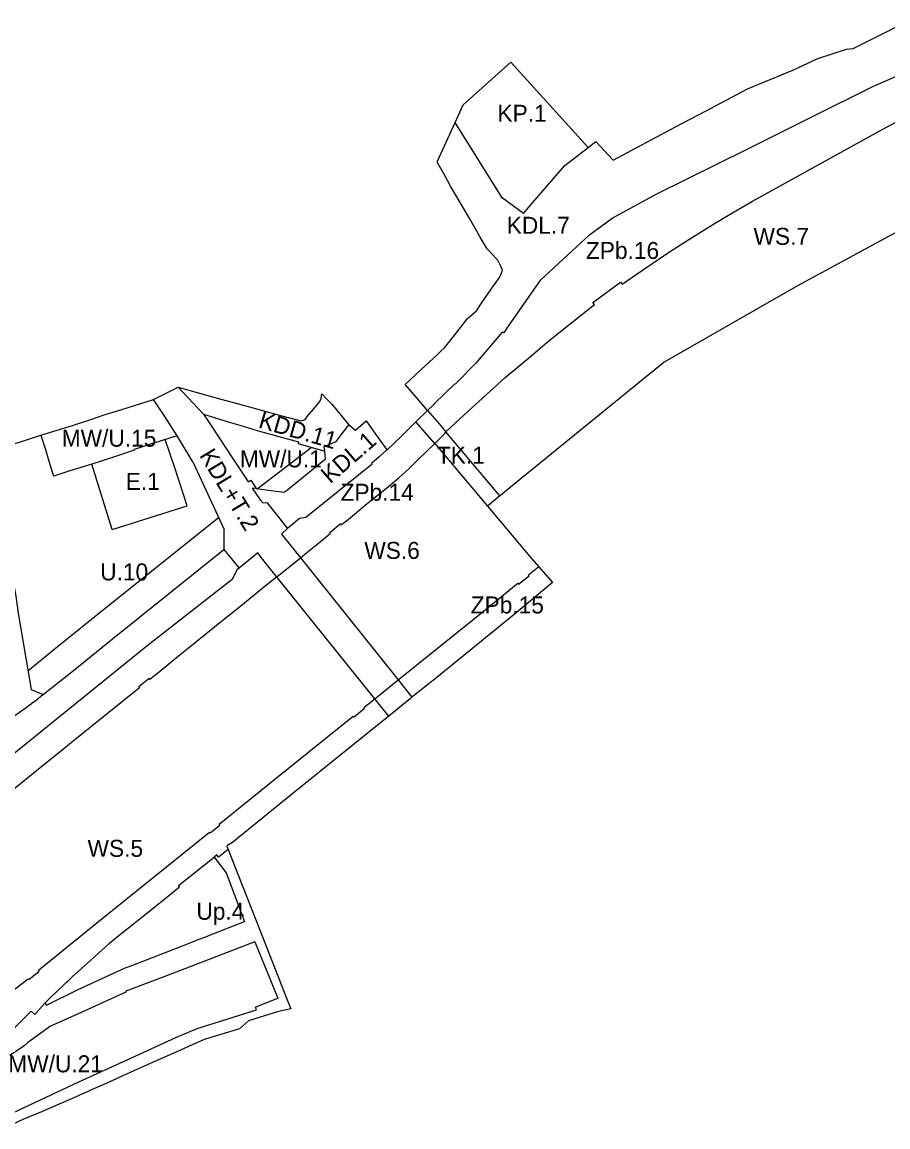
# Model space of a CAD drawing. Extents: x 7421697 to 7426767, y 5545731 to 5547485.
# Drawn here: x 7424808 to 7425420, y 5546077 to 5546858 of the extents above; entities that cross this region are included whole.
import ezdxf

# ---------------------------------------------------------------- set-up
doc = ezdxf.new("R2010")
doc.units = 0
for name, color, linetype in [('LIN_Linia Zabudowy Nieprzekraczalna', 7, 'Continuous'), ('LIN_linie rozgraniczające terenu WS', 7, 'Continuous'), ('LIN_linie_rozgraniczajace', 7, 'Continuous'), ('TXT_oznaczenia_przeznaczen', 7, 'Continuous')]:
    doc.layers.add(name, color=color, linetype=linetype)

msp = doc.modelspace()

# ---------------------------------------------------------------- linework, layer by layer
at = {"layer": 'LIN_Linia Zabudowy Nieprzekraczalna'}
msp.add_line((7424974.16, 5546528.08), (7425012.34, 5546557.27), dxfattribs=at)
msp.add_lwpolyline([(7424812.12, 5546399.5), (7424832.88, 5546416.23), (7424859.51, 5546437.7), (7424946.91, 5546507.81)], dxfattribs=at)
at = {"layer": 'LIN_linie rozgraniczające terenu WS'}
for p, q in [((7424988.11, 5546465.87), (7425004.76, 5546479.32)), ((7425057.27, 5546379.65), (7425073.85, 5546392.93))]:
    msp.add_line(p, q, dxfattribs=at)
msp.add_lwpolyline([(7425099.74, 5546560.06), (7425106.95, 5546567.12), (7425107.66, 5546568.17)], dxfattribs=at)
at = {"layer": 'LIN_linie_rozgraniczajace'}
for p, q in [((7425099.74, 5546560.06), (7425086.39, 5546575.21)), ((7425145.83, 5546523), (7425107.66, 5546568.17)), ((7425099.74, 5546560.06), (7425137.02, 5546515.83)), ((7424871.65, 5546499.22), (7424857.22, 5546545.47)), ((7424972.54, 5546207.92), (7424988.84, 5546168.02))]:
    msp.add_line(p, q, dxfattribs=at)
for points in [[(7424799.61, 5546558.88), (7424821.33, 5546565.81), (7424832.92, 5546569.44), (7424844.36, 5546573.07), (7424855.79, 5546576.7), (7424866.75, 5546580.41), (7424878.58, 5546584.06), (7424900.98, 5546591.12), (7424918.38, 5546599.75), (7424933.46, 5546595.59), (7424948.55, 5546591.43), (7424961.05, 5546588.01), (7424991.7, 5546579.66), (7425005.24, 5546575.97), (7425008.11, 5546576.92), (7425009.64, 5546579), (7425014.08, 5546584.36), (7425018.52, 5546589.72), (7425019.53, 5546591.91), (7425019.91, 5546595.02), (7425023.45, 5546591.36), (7425027, 5546587.7), (7425038.9, 5546573.3), (7425041.24, 5546571.43), (7425043.82, 5546569.36), (7425051.22, 5546576.08), (7425055.05, 5546570.66), (7425065.79, 5546555.44), (7425065.84, 5546555.36), (7425076.12, 5546565.29), (7425086.39, 5546575.21), (7425094.68, 5546583.27), (7425086.78, 5546592.47), (7425078.87, 5546601.67), (7425090.16, 5546612.2), (7425101.46, 5546622.74), (7425104.03, 5546625.14), (7425106.59, 5546627.55), (7425114.78, 5546637.95), (7425122.96, 5546648.35), (7425129.19, 5546653.8), (7425133.85, 5546660.53), (7425139.71, 5546668.94), (7425145.58, 5546677.35), (7425146.62, 5546679.93), (7425147.67, 5546682.52), (7425146.16, 5546685.76), (7425144.66, 5546689.01), (7425140.78, 5546693.22), (7425136.89, 5546697.42), (7425134.31, 5546701.86), (7425131.72, 5546706.29), (7425124.49, 5546718.66), (7425117.69, 5546730.27), (7425110.89, 5546741.88), (7425106.58, 5546749.77), (7425102.27, 5546757.66), (7425101.36, 5546759.07), (7425114.14, 5546786.84), (7425119.92, 5546799.25), (7425153.43, 5546829.48), (7425208.12, 5546769.05), (7425213.67, 5546773.31), (7425225.89, 5546760.2), (7425269.84, 5546783.7), (7425291.13, 5546794.9), (7425320.74, 5546810.47), (7425352.83, 5546823.71), (7425370.5, 5546831.95), (7425390.91, 5546838.71), (7425395.55, 5546839), (7425432.72, 5546857.72)], [(7425150.26, 5546640.53), (7425174.69, 5546675.57), (7425209.13, 5546707.54), (7425225.24, 5546719.13), (7425256.82, 5546736.38), (7425320.57, 5546768.05), (7425366.22, 5546790.77), (7425409.84, 5546812.52), (7425454.91, 5546831.93), (7425462.33, 5546834.59), (7425472.1, 5546838.09), (7425490.62, 5546843.04), (7425509.4, 5546848.46), (7425520.77, 5546850.87), (7425531.3, 5546848.51)], [(7425168.77, 5546622.63), (7425179.18, 5546631.49), (7425195.51, 5546644.63), (7425212.72, 5546658.14), (7425211.46, 5546659.7), (7425231.15, 5546674.09), (7425232.29, 5546672.55), (7425246.51, 5546682.57), (7425265.76, 5546695.52), (7425281.92, 5546705.87), (7425297.56, 5546715.53), (7425301, 5546717.59), (7425312.66, 5546724.34), (7425324.32, 5546731.1), (7425413.84, 5546780.71), (7425439.34, 5546794.38), (7425453.06, 5546801.44), (7425472.41, 5546810.87), (7425492.07, 5546819.93), (7425518.89, 5546831.06), (7425536.41, 5546837.33), (7425547.13, 5546840.63)], [(7425162.42, 5546722.56), (7425147.46, 5546733.56), (7425114.14, 5546786.84)], [(7425162.42, 5546722.56), (7425168.95, 5546730.11), (7425191.75, 5546756.46), (7425208.12, 5546769.05)], [(7425432.35, 5546712.59), (7425356.22, 5546671.39), (7425261.83, 5546617.35), (7425154.53, 5546530.08), (7425146.14, 5546523.24), (7425145.83, 5546523), (7425138.13, 5546516.73), (7425137.02, 5546515.83), (7425168.21, 5546478.7), (7425173.22, 5546472.96), (7425183.03, 5546461.75), (7425155.91, 5546439.18), (7425100.05, 5546393.63), (7425083.65, 5546380.67), (7425082.63, 5546379.87), (7425067.33, 5546367.48), (7425050.61, 5546354.02), (7424999.71, 5546312.89), (7424956.76, 5546278.19), (7424952.83, 5546275.68), (7424953.78, 5546273.19), (7424958.33, 5546261.26), (7424978.44, 5546210.29), (7424995.51, 5546167.01), (7424998.07, 5546160.52), (7424989.29, 5546158.65), (7424968.14, 5546152.12), (7424961.67, 5546146.44), (7424936.81, 5546138.91), (7424925.75, 5546133.94), (7424919.95, 5546131.4), (7424904.46, 5546124.56), (7424894.34, 5546120.04), (7424879.74, 5546113.49), (7424867.95, 5546108.17), (7424865.81, 5546107.22), (7424857.48, 5546103.49), (7424853.07, 5546101.52), (7424849.19, 5546099.79), (7424846.77, 5546098.71), (7424821.65, 5546087.94), (7424808.45, 5546082.3), (7424797.36, 5546077.18)], [(7425150.26, 5546640.53), (7425148.4, 5546638.24), (7425147.69, 5546638.87), (7425128.58, 5546616.6), (7425124.42, 5546612.36), (7425120.26, 5546608.12), (7425114.18, 5546601.86), (7425113.89, 5546602.14), (7425106.79, 5546595.23), (7425099.68, 5546588.31), (7425098.77, 5546587.39), (7425094.68, 5546583.27)], [(7425107.66, 5546568.17), (7425117.59, 5546577.52), (7425149.58, 5546606.7), (7425168.77, 5546622.63)], [(7424918.38, 5546599.75), (7424936.3, 5546580.66), (7424937.67, 5546578.57), (7424942.28, 5546571.55), (7424956.7, 5546549.56), (7424965.17, 5546536.87), (7424967.77, 5546532.99), (7424969.61, 5546534.13), (7424973.56, 5546528.16), (7424992.94, 5546525.64), (7424995.91, 5546527.54), (7425022.52, 5546549.28), (7425021.96, 5546554.53), (7425021.6, 5546557.85), (7425030.05, 5546561.43), (7425038.9, 5546573.3)], [(7424928.77, 5546547.03), (7424917.59, 5546565.52), (7424912.66, 5546573.16), (7424912.72, 5546573.21), (7424908.42, 5546579.75), (7424901, 5546591.13)], [(7424936.3, 5546580.66), (7424953.81, 5546575.36), (7424961.85, 5546572.93), (7424974.2, 5546569.2), (7424989.56, 5546564.96), (7425003.36, 5546561.07), (7425003.1, 5546559.9), (7425021.96, 5546554.53)], [(7425094.68, 5546583.27), (7425102.77, 5546573.86), (7425107.66, 5546568.17)], [(7424821.33, 5546565.81), (7424824.3, 5546556.46), (7424827.19, 5546546.77), (7424830.32, 5546536.95)], [(7424917.59, 5546565.52), (7424912.82, 5546563.96), (7424911.58, 5546563.55), (7424910.34, 5546563.15), (7424909.26, 5546562.8), (7424904.96, 5546561.4), (7424898.67, 5546559.45), (7424892.37, 5546557.49), (7424887.15, 5546555.71), (7424887.24, 5546555.34), (7424876.11, 5546551.62), (7424864.51, 5546547.75), (7424857.22, 5546545.47), (7424841.69, 5546540.62), (7424831.26, 5546537.24), (7424830.32, 5546536.95)], [(7424871.65, 5546499.22), (7424924.68, 5546515.85), (7424915.96, 5546542.9), (7424909.26, 5546562.8)], [(7425004.76, 5546479.32), (7425009.21, 5546482.91), (7425016.44, 5546488.73), (7425021.29, 5546492.66), (7425026.13, 5546496.58), (7425025.59, 5546497.24), (7425032.96, 5546503.18), (7425033.45, 5546502.52), (7425037.31, 5546505.47), (7425042.97, 5546510.14), (7425047.51, 5546513.83), (7425052.05, 5546517.53), (7425065.58, 5546528.4), (7425074.45, 5546535.71), (7425081.31, 5546542.09), (7425087.54, 5546548.18), (7425099.74, 5546560.06)], [(7425065.79, 5546555.44), (7425060.55, 5546550.62), (7425055.03, 5546545.91), (7425055.49, 5546545.34), (7425008.68, 5546507.73), (7425005.77, 5546507.28), (7425004.07, 5546506.9), (7424995.62, 5546499.84), (7424991.43, 5546495.98), (7425005.91, 5546477.88), (7425073.85, 5546392.93), (7425083.65, 5546380.67)], [(7424928.77, 5546547.03), (7424950.94, 5546499.17), (7424950.6, 5546498.87), (7424950.72, 5546485.16)], [(7424973.56, 5546528.16), (7424970.76, 5546528.51), (7424976.24, 5546520.3), (7424978.1, 5546518.13), (7424981.01, 5546518.32), (7424995.62, 5546499.84)], [(7424822.97, 5546382.56), (7424845.44, 5546400.66), (7424872.04, 5546422.11), (7424950.72, 5546485.16), (7424961.42, 5546471.98), (7424959.87, 5546470.73), (7424956.58, 5546463.82), (7424896.17, 5546416.91), (7424774.86, 5546318.83), (7424711.72, 5546268.13), (7424695.62, 5546255.91), (7424679.64, 5546244.15), (7424664.13, 5546233.37), (7424653.19, 5546226.32), (7424640.7, 5546218.87)], [(7425067.33, 5546367.48), (7425057.27, 5546379.65), (7424988.68, 5546465.16), (7424976.39, 5546480.49), (7424974.63, 5546482.67), (7424961.42, 5546471.98)], [(7425073.85, 5546392.94), (7425126.59, 5546435.49), (7425158.41, 5546461.26), (7425158.98, 5546460.65), (7425166.54, 5546466.58), (7425166.09, 5546467.2), (7425173.11, 5546472.87), (7425173.22, 5546472.96)], [(7424988.11, 5546465.87), (7424977.2, 5546457.04), (7424962.56, 5546445.16), (7424946.66, 5546432.35), (7424932.91, 5546421.23), (7424917.25, 5546408.59), (7424904.81, 5546398.54), (7424898.36, 5546393.38), (7424897.87, 5546393.98), (7424890.45, 5546388.01), (7424890.99, 5546387.38), (7424868.22, 5546369.06), (7424845.35, 5546350.61), (7424837.44, 5546344.22), (7424821.96, 5546331.72), (7424799.35, 5546313.46)], [(7424802.25, 5546459.86), (7424803.55, 5546452.04), (7424805.29, 5546440.02), (7424814.36, 5546386.26), (7424822.97, 5546382.56)], [(7424661.5, 5546077.85), (7424674.13, 5546085.55), (7424674.6, 5546084.85), (7424682.6, 5546089.82), (7424682.16, 5546090.62), (7424703.77, 5546103.94), (7424759.9, 5546141.92), (7424812.22, 5546181.85), (7424812.78, 5546181.29), (7424819.99, 5546187.21), (7424819.56, 5546187.81), (7424862.07, 5546222.28), (7424940.6, 5546285.37), (7424941.01, 5546284.88), (7424947.89, 5546290.38), (7424947.41, 5546291.07), (7424989.15, 5546324.66), (7425042.17, 5546367.38), (7425042.68, 5546366.91), (7425050.01, 5546372.94), (7425049.68, 5546373.37), (7425057.27, 5546379.65)], [(7424822.97, 5546382.56), (7424817.62, 5546378.25), (7424815.92, 5546376.99), (7424813.83, 5546375.46), (7424811.74, 5546373.94), (7424802.97, 5546367.53)], [(7424824.01, 5546164.62), (7424827.92, 5546168.38), (7424837.32, 5546177.38), (7424839.15, 5546179.15), (7424840.98, 5546180.91), (7424843.44, 5546183.26), (7424856.53, 5546195), (7424869.62, 5546206.73), (7424871.55, 5546208.46), (7424877.84, 5546213.49), (7424881.21, 5546216.2), (7424886.8, 5546220.7), (7424889.02, 5546222.49), (7424904.13, 5546234.63), (7424919.24, 5546246.77), (7424918.57, 5546247.79), (7424943.82, 5546267.82)], [(7424953.78, 5546273.19), (7424946.95, 5546267.7), (7424945.75, 5546269.37), (7424943.82, 5546267.82), (7424952.24, 5546256.63), (7424965.34, 5546222.37)], [(7424726.02, 5546100.65), (7424729.7, 5546094.76), (7424785.69, 5546132.59), (7424799.27, 5546143.76), (7424814.44, 5546158.92), (7424817.02, 5546156.64), (7424824.01, 5546164.62), (7424825.31, 5546163.3), (7424847.73, 5546174.18), (7424880.46, 5546189.25), (7424887.59, 5546192.02), (7424920.27, 5546204.59), (7424932.07, 5546209.24), (7424938.37, 5546211.81), (7424940.05, 5546212.41), (7424965.34, 5546222.37)], [(7424972.54, 5546207.92), (7424917.05, 5546186.47), (7424899.43, 5546179.82), (7424881.27, 5546172.97), (7424881.44, 5546172.36), (7424844.53, 5546155.69), (7424828.12, 5546148.24), (7424811.88, 5546136.63), (7424809.47, 5546134.53), (7424799.3, 5546127.52)], [(7424785.77, 5546079.88), (7424848.07, 5546108.93), (7424882.4, 5546124.64), (7424916.72, 5546140.34), (7424931.8, 5546146.67), (7424973.81, 5546159.95), (7424973, 5546161.89), (7424974.07, 5546162.31), (7424988.84, 5546168.02)]]:
    msp.add_lwpolyline(points, dxfattribs=at)

# ---------------------------------------------------------------- texts
at = {"layer": 'TXT_oznaczenia_przeznaczen'}
for s, p in [('KP.1', (7425144.09, 5546787.28)), ('KDL.7', (7425150.62, 5546708.18)), ('WS.7', (7425325.11, 5546700.36)), ('ZPb.16', (7425206.64, 5546690.38)), ('MW/U.15', (7424836.06, 5546557.76)), ('TK.1', (7425101.25, 5546545.68)), ('MW/U.1', (7424961.93, 5546543.15)), ('E.1', (7424881.28, 5546527.2)), ('ZPb.14', (7425033.19, 5546519.53)), ('WS.6', (7425049.96, 5546478.48)), ('U.10', (7424863.24, 5546463.27)), ('ZPb.15', (7425125.16, 5546439.91)), ('WS.5', (7424854.3, 5546267.99)), ('Up.4', (7424931.23, 5546223.5)), ('MW/U.21', (7424798.29, 5546115.75))]:
    msp.add_text(s, height=12, dxfattribs=at).set_placement(p)
for s, rotation, p in [('KDD.11', 343.95497, (7424974.5, 5546571.4)), ('KDL.1', 40.96063, (7425025.8, 5546531.15)), ('KDL+T.2', 301.22966, (7424932.98, 5546551.65))]:
    msp.add_text(s, height=12, rotation=rotation, dxfattribs=at).set_placement(p)

doc.saveas('drawing.dxf')
